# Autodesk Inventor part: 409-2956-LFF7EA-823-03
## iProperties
Created: 2010-09
Part Number: 409-2956-LFF7EA-823-03
Material: 3/8" OD TUBE - SS
Document SubType Name: Modeling
Designer: S. Boerckel
Engineer: Steve Boerckel
Mass: 61.6007 g
Surface Area: 127.01 cm^2
Volume: 7.62385 cm^3
Density: 8.08 g/cm^3
Description: PRESSURE DIFF TUBE
LGTH: 1.750 in
Author: S. Boerckel
Revision Number: 0
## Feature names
1. Sweep3
